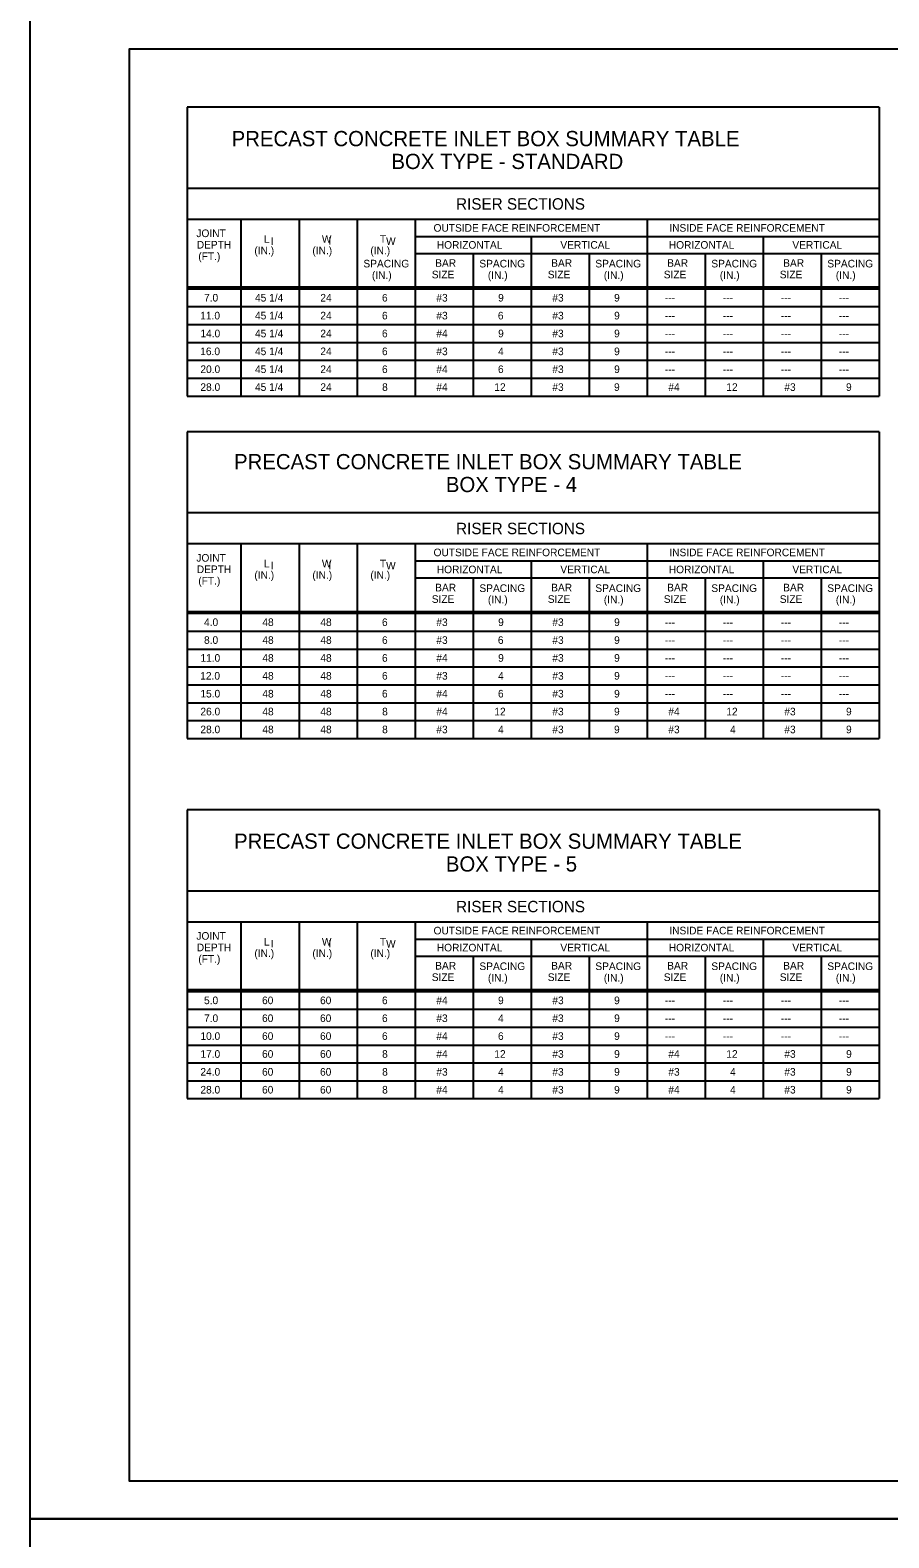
# Model space of a CAD drawing. Extents: x -6420 to 49575, y -4552 to 11624.
# Drawn here: x -6420 to -5310, y -94 to 1855 of the extents above; entities that cross this region are included whole.
import ezdxf

# ---------------------------------------------------------------- set-up
doc = ezdxf.new("R2010")
doc.units = 0
doc.layers.add('1', color=7, linetype='Continuous')
doc.layers.add('PLT-BNDY', color=7, linetype='Continuous')

msp = doc.modelspace()

# ---------------------------------------------------------------- linework, layer by layer
at = {"layer": '1'}
for p, q in [((-6217.4, 1755.6), (-6217.4, 1382.3)), ((-5322.4, 1755.6), (-6217.4, 1755.6)), ((-5322.4, 1755.6), (-5322.4, 1382.3)), ((-5322.4, 1650.6), (-6217.4, 1650.6)), ((-5322.4, 1610.6), (-6217.4, 1610.6)), ((-6147.4, 1382.3), (-6147.4, 1610.6)), ((-6072.4, 1610.6), (-6072.4, 1382.3)), ((-5997.4, 1610.6), (-5997.4, 1382.3)), ((-5922.4, 1610.6), (-5922.4, 1382.3)), ((-5622.4, 1610.6), (-5622.4, 1382.3)), ((-5922.4, 1588.6), (-5622.4, 1588.6)), ((-5772.4, 1588.6), (-5772.4, 1382.3)), ((-5622.4, 1588.6), (-5322.4, 1588.6)), ((-5472.4, 1588.6), (-5472.4, 1382.3)), ((-5922.4, 1566.6), (-5622.4, 1566.6)), ((-5847.4, 1566.6), (-5847.4, 1382.3)), ((-5697.4, 1566.6), (-5697.4, 1382.3)), ((-5622.4, 1566.6), (-5322.4, 1566.6)), ((-5547.4, 1566.6), (-5547.4, 1382.3)), ((-5397.4, 1566.6), (-5397.4, 1382.3)), ((-6217.4, 1523.4), (-5322.4, 1523.4)), ((-6217.4, 1520.9), (-5322.4, 1520.9)), ((-6217.4, 1497.8), (-5322.4, 1497.8)), ((-6217.4, 1474.7), (-5322.4, 1474.7)), ((-6217.4, 1451.6), (-5322.4, 1451.6)), ((-6217.4, 1428.5), (-5322.4, 1428.5)), ((-6217.4, 1405.4), (-5322.4, 1405.4)), ((-6217.4, 1382.3), (-5322.4, 1382.3)), ((-6217.4, 1336.1), (-6217.4, 939.7)), ((-5322.4, 1336.1), (-6217.4, 1336.1)), ((-5322.4, 1336.1), (-5322.4, 939.7)), ((-5322.4, 1231.1), (-6217.4, 1231.1)), ((-5322.4, 1191.1), (-6217.4, 1191.1)), ((-6147.4, 939.7), (-6147.4, 1191.1)), ((-6072.4, 1191.1), (-6072.4, 939.7)), ((-5997.4, 1191.1), (-5997.4, 939.7)), ((-5922.4, 1191.1), (-5922.4, 939.7)), ((-5622.4, 1191.1), (-5622.4, 939.7)), ((-5922.4, 1169.1), (-5622.4, 1169.1)), ((-5772.4, 1169.1), (-5772.4, 939.7)), ((-5622.4, 1169.1), (-5322.4, 1169.1)), ((-5472.4, 1169.1), (-5472.4, 939.7)), ((-5922.4, 1147.1), (-5622.4, 1147.1)), ((-5847.4, 1147.1), (-5847.4, 939.7)), ((-5697.4, 1147.1), (-5697.4, 939.7)), ((-5622.4, 1147.1), (-5322.4, 1147.1)), ((-5547.4, 1147.1), (-5547.4, 939.7)), ((-5397.4, 1147.1), (-5397.4, 939.7)), ((-6217.4, 1103.9), (-5322.4, 1103.9)), ((-6217.4, 1101.4), (-5322.4, 1101.4)), ((-6217.4, 1078.3), (-5322.4, 1078.3)), ((-6217.4, 1055.2), (-5322.4, 1055.2)), ((-6217.4, 1032.1), (-5322.4, 1032.1)), ((-6217.4, 1009), (-5322.4, 1009)), ((-6217.4, 985.9), (-5322.4, 985.9)), ((-6217.4, 962.8), (-5322.4, 962.8)), ((-6217.4, 939.7), (-5322.4, 939.7)), ((-6217.4, 847.3), (-6217.4, 474.1)), ((-5322.4, 847.3), (-6217.4, 847.3)), ((-5322.4, 847.3), (-5322.4, 474.1)), ((-5322.4, 742.4), (-6217.4, 742.4)), ((-5322.4, 702.4), (-6217.4, 702.4)), ((-6147.4, 474.1), (-6147.4, 702.4)), ((-6072.4, 702.4), (-6072.4, 474.1)), ((-5997.4, 702.4), (-5997.4, 474.1)), ((-5922.4, 702.4), (-5922.4, 474.1)), ((-5622.4, 702.4), (-5622.4, 474.1)), ((-5922.4, 680.4), (-5622.4, 680.4)), ((-5772.4, 680.4), (-5772.4, 474.1)), ((-5622.4, 680.4), (-5322.4, 680.4)), ((-5472.4, 680.4), (-5472.4, 474.1)), ((-5922.4, 658.4), (-5622.4, 658.4)), ((-5847.4, 658.4), (-5847.4, 474.1)), ((-5697.4, 658.4), (-5697.4, 474.1)), ((-5622.4, 658.4), (-5322.4, 658.4)), ((-5547.4, 658.4), (-5547.4, 474.1)), ((-5397.4, 658.4), (-5397.4, 474.1)), ((-6217.4, 615.1), (-5322.4, 615.1)), ((-6217.4, 612.7), (-5322.4, 612.7)), ((-6217.4, 589.6), (-5322.4, 589.6)), ((-6217.4, 566.5), (-5322.4, 566.5)), ((-6217.4, 543.4), (-5322.4, 543.4)), ((-6217.4, 520.3), (-5322.4, 520.3)), ((-6217.4, 497.2), (-5322.4, 497.2)), ((-6217.4, 474.1), (-5322.4, 474.1))]:
    msp.add_line(p, q, dxfattribs=at)
msp.add_lwpolyline([(-3713.7, -19.8), (-3713.7, 1830.6), (-6292.4, 1830.6), (-6292.4, -19.8), (-3713.7, -19.8), (-3713.7, 66.7), (-4369.8, 66.7), (-4369.8, 278.9), (-3713.7, 278.9), (-3713.7, 373.9), (-4369.8, 373.9), (-4369.8, -19.8), (-4111.3, -19.8), (-4111.3, 66.7), (-4111.3, -19.8), (-3858.7, -19.8), (-3858.7, 66.7), (-3858.7, 26.3), (-3713.7, 26.3)], dxfattribs=at)
at = {"layer": 'PLT-BNDY'}
for points in [[(-6420.4, 1879.8), (-3661.2, 1879.8), (-3661.2, -69), (-6420.4, -69)], [(-6420.4, -69), (-3661.2, -69), (-3661.2, -2017.8), (-6420.4, -2017.8)]]:
    msp.add_lwpolyline(points, close=True, dxfattribs=at)

# ---------------------------------------------------------------- texts
at = {"layer": '1'}
for s, height, p in [('PRECAST CONCRETE INLET BOX SUMMARY TABLE', 19.685, (-6159.8, 1705.2)), ('BOX TYPE - STANDARD', 19.685, (-5953.2, 1675.7)), ('RISER SECTIONS', 14.764, (-5869.6, 1623.2)), ('OUTSIDE FACE REINFORCEMENT', 9.843, (-5898.7, 1594.7)), ('INSIDE FACE REINFORCEMENT', 9.843, (-5593.8, 1594.7)), ('JOINT', 9.84, (-6205.4, 1587.7)), ('DEPTH', 9.84, (-6204.9, 1572.9)), ('L ', 9.84, (-6118.1, 1580.3)), ('I', 9.84, (-6109.1, 1577.7)), ('W ', 9.84, (-6043.1, 1580.3)), ('I', 9.84, (-6034.7, 1577.8)), ('T ', 9.84, (-5968.1, 1580.3)), ('W', 9.84, (-5960.1, 1577.6)), ('HORIZONTAL', 9.84, (-5894.5, 1572.7)), ('VERTICAL', 9.84, (-5734.7, 1572.7)), ('HORIZONTAL', 9.84, (-5594.5, 1572.7)), ('VERTICAL', 9.84, (-5434.7, 1572.7)), ('(FT.)', 9.84, (-6202.9, 1558)), ('(IN.)', 9.84, (-6130.4, 1565.5)), ('(IN.)', 9.84, (-6055.4, 1565.5)), ('(IN.)', 9.84, (-5980.4, 1565.5)), ('BAR', 9.84, (-5896.6, 1549.3)), ('BAR', 9.84, (-5746.6, 1549.3)), ('BAR', 9.84, (-5596.6, 1549.3)), ('BAR', 9.84, (-5446.6, 1549.3)), ('SPACING', 9.84, (-5989.4, 1548.5)), ('(IN.)', 9.84, (-5978.4, 1533.7)), ('SIZE', 9.84, (-5901, 1534.4)), ('SPACING', 9.84, (-5839.5, 1548.5)), ('(IN.)', 9.84, (-5828.5, 1533.7)), ('SIZE', 9.84, (-5751, 1534.4)), ('SPACING', 9.84, (-5689.5, 1548.5)), ('(IN.)', 9.84, (-5678.5, 1533.7)), ('SIZE', 9.84, (-5601, 1534.4)), ('SPACING', 9.84, (-5539.5, 1548.5)), ('(IN.)', 9.84, (-5528.5, 1533.7)), ('SIZE', 9.84, (-5451, 1534.4)), ('SPACING', 9.84, (-5389.5, 1548.5)), ('(IN.)', 9.84, (-5378.5, 1533.7)), ('7.0', 9.84, (-6195.5, 1504.4)), ('45 1/4', 9.84, (-6129.6, 1504.4)), ('24', 9.84, (-6045.1, 1504.4)), ('6', 9.84, (-5965.4, 1504.4)), ('#3', 9.84, (-5895.1, 1504.4)), ('9', 9.84, (-5815.2, 1504.4)), ('#3', 9.84, (-5745.1, 1504.4)), ('9', 9.84, (-5665.2, 1504.4)), ('---', 9.84, (-5599.6, 1504.4)), ('---', 9.84, (-5524.6, 1504.4)), ('---', 9.84, (-5449.6, 1504.4)), ('---', 9.84, (-5374.6, 1504.4)), ('11.0', 9.84, (-6200.4, 1481.3)), ('45 1/4', 9.84, (-6129.6, 1481.3)), ('24', 9.84, (-6045.1, 1481.3)), ('6', 9.84, (-5965.4, 1481.3)), ('#3', 9.84, (-5895.1, 1481.3)), ('6', 9.84, (-5815.5, 1481.3)), ('#3', 9.84, (-5745.1, 1481.3)), ('9', 9.84, (-5665.2, 1481.3)), ('---', 9.84, (-5599.6, 1481.3)), ('---', 9.84, (-5524.6, 1481.3)), ('---', 9.84, (-5449.6, 1481.3)), ('---', 9.84, (-5374.6, 1481.3)), ('14.0', 9.84, (-6200.2, 1458.2)), ('45 1/4', 9.84, (-6129.6, 1458.2)), ('24', 9.84, (-6045.1, 1458.2)), ('6', 9.84, (-5965.4, 1458.2)), ('#4', 9.84, (-5895.1, 1458.2)), ('9', 9.84, (-5815.2, 1458.2)), ('#3', 9.84, (-5745.1, 1458.2)), ('9', 9.84, (-5665.2, 1458.2)), ('---', 9.84, (-5599.6, 1458.2)), ('---', 9.84, (-5524.6, 1458.2)), ('---', 9.84, (-5449.6, 1458.2)), ('---', 9.84, (-5374.6, 1458.2)), ('16.0', 9.84, (-6200.4, 1435.1)), ('45 1/4', 9.84, (-6129.6, 1435.1)), ('24', 9.84, (-6045.1, 1435.1)), ('6', 9.84, (-5965.4, 1435.1)), ('#3', 9.84, (-5895.1, 1435.1)), ('4', 9.84, (-5815.2, 1435.1)), ('#3', 9.84, (-5745.1, 1435.1)), ('9', 9.84, (-5665.2, 1435.1)), ('---', 9.84, (-5599.6, 1435.1)), ('---', 9.84, (-5524.6, 1435.1)), ('---', 9.84, (-5449.6, 1435.1)), ('---', 9.84, (-5374.6, 1435.1)), ('20.0', 9.84, (-6200.2, 1412)), ('45 1/4', 9.84, (-6129.6, 1412)), ('24', 9.84, (-6045.1, 1412)), ('6', 9.84, (-5965.4, 1412)), ('#4', 9.84, (-5895.1, 1412)), ('6', 9.84, (-5815.4, 1412)), ('#3', 9.84, (-5745.1, 1412)), ('9', 9.84, (-5665.2, 1412)), ('---', 9.84, (-5599.6, 1412)), ('---', 9.84, (-5524.6, 1412)), ('---', 9.84, (-5449.6, 1412)), ('---', 9.84, (-5374.6, 1412)), ('28.0', 9.84, (-6200.2, 1388.9)), ('45 1/4', 9.84, (-6129.6, 1388.9)), ('24', 9.84, (-6045.1, 1388.9)), ('8', 9.84, (-5965.2, 1388.9)), ('#4', 9.84, (-5895.1, 1388.9)), ('12', 9.84, (-5820.1, 1388.9)), ('#3', 9.84, (-5745.1, 1388.9)), ('9', 9.84, (-5665.3, 1388.9)), ('#4', 9.84, (-5595.1, 1388.9)), ('12', 9.84, (-5520.1, 1388.9)), ('#3', 9.84, (-5445.1, 1388.9)), ('9', 9.84, (-5365.3, 1388.9)), ('PRECAST CONCRETE INLET BOX SUMMARY TABLE', 19.685, (-6156.7, 1287.6)), ('BOX TYPE - 4', 19.685, (-5882.8, 1258.1)), ('RISER SECTIONS', 14.764, (-5869.6, 1203.7)), ('JOINT', 9.84, (-6205.4, 1168.2)), ('L ', 9.84, (-6118.1, 1160.8)), ('W ', 9.84, (-6043.1, 1160.8)), ('T ', 9.84, (-5968.1, 1160.8)), ('OUTSIDE FACE REINFORCEMENT', 9.843, (-5898.7, 1175.2)), ('INSIDE FACE REINFORCEMENT', 9.843, (-5593.8, 1175.2)), ('DEPTH', 9.84, (-6204.9, 1153.4)), ('(IN.)', 9.84, (-6130.4, 1146)), ('I', 9.84, (-6109.1, 1158.3)), ('(IN.)', 9.84, (-6055.4, 1146)), ('I', 9.84, (-6034.7, 1158.3)), ('(IN.)', 9.84, (-5980.4, 1146)), ('W', 9.84, (-5960.1, 1158.1)), ('HORIZONTAL', 9.84, (-5894.5, 1153.2)), ('VERTICAL', 9.84, (-5734.7, 1153.2)), ('HORIZONTAL', 9.84, (-5594.5, 1153.2)), ('VERTICAL', 9.84, (-5434.7, 1153.2)), ('(FT.)', 9.84, (-6202.9, 1138.6)), ('BAR', 9.84, (-5896.6, 1129.8)), ('SPACING', 9.84, (-5839.4, 1129)), ('BAR', 9.84, (-5746.6, 1129.8)), ('SPACING', 9.84, (-5689.5, 1129)), ('BAR', 9.84, (-5596.6, 1129.8)), ('SPACING', 9.84, (-5539.5, 1129)), ('BAR', 9.84, (-5446.6, 1129.8)), ('SPACING', 9.84, (-5389.5, 1129)), ('SIZE', 9.84, (-5901, 1114.9)), ('(IN.)', 9.84, (-5828.4, 1114.2)), ('SIZE', 9.84, (-5751, 1114.9)), ('(IN.)', 9.84, (-5678.5, 1114.2)), ('SIZE', 9.84, (-5601, 1114.9)), ('(IN.)', 9.84, (-5528.5, 1114.2)), ('SIZE', 9.84, (-5451, 1114.9)), ('(IN.)', 9.84, (-5378.5, 1114.2)), ('4.0', 9.84, (-6195.5, 1085)), ('48', 9.84, (-6120.1, 1085)), ('48', 9.84, (-6045.1, 1085)), ('6', 9.84, (-5965.4, 1085)), ('#3', 9.84, (-5895.1, 1085)), ('9', 9.84, (-5815.2, 1085)), ('#3', 9.84, (-5745.1, 1085)), ('9', 9.84, (-5665.2, 1085)), ('#3', 9.84, (-5745.1, 1061.9)), ('---', 9.84, (-5599.6, 1085)), ('---', 9.84, (-5524.6, 1085)), ('---', 9.84, (-5449.6, 1085)), ('---', 9.84, (-5374.6, 1085)), ('8.0', 9.84, (-6195.5, 1061.9)), ('48', 9.84, (-6120.1, 1061.9)), ('48', 9.84, (-6045.1, 1061.9)), ('6', 9.84, (-5965.4, 1061.9)), ('#3', 9.84, (-5895.1, 1061.9)), ('6', 9.84, (-5815.5, 1061.9)), ('9', 9.84, (-5665.2, 1061.9)), ('---', 9.84, (-5599.6, 1061.9)), ('---', 9.84, (-5524.6, 1061.9)), ('---', 9.84, (-5449.6, 1061.9)), ('---', 9.84, (-5374.6, 1061.9)), ('11.0', 9.84, (-6200.2, 1038.8)), ('48', 9.84, (-6120.1, 1038.8)), ('48', 9.84, (-6045.1, 1038.8)), ('6', 9.84, (-5965.4, 1038.8)), ('#4', 9.84, (-5895.1, 1038.8)), ('9', 9.84, (-5815.2, 1038.8)), ('#3', 9.84, (-5745.1, 1038.8)), ('9', 9.84, (-5665.2, 1038.8)), ('---', 9.84, (-5599.6, 1038.8)), ('---', 9.84, (-5524.6, 1038.8)), ('---', 9.84, (-5449.6, 1038.8)), ('---', 9.84, (-5374.6, 1038.8)), ('12.0', 9.84, (-6200.4, 1015.7)), ('48', 9.84, (-6120.1, 1015.7)), ('48', 9.84, (-6045.1, 1015.7)), ('6', 9.84, (-5965.4, 1015.7)), ('#3', 9.84, (-5895.1, 1015.7)), ('4', 9.84, (-5815.2, 1015.7)), ('#3', 9.84, (-5745.1, 1015.7)), ('9', 9.84, (-5665.2, 1015.7)), ('---', 9.84, (-5599.6, 1015.7)), ('---', 9.84, (-5524.6, 1015.7)), ('---', 9.84, (-5449.6, 1015.7)), ('---', 9.84, (-5374.6, 1015.7)), ('15.0', 9.84, (-6200.2, 992.6)), ('48', 9.84, (-6120.1, 992.6)), ('48', 9.84, (-6045.1, 992.6)), ('6', 9.84, (-5965.4, 992.6)), ('#4', 9.84, (-5895.1, 992.6)), ('6', 9.84, (-5815.4, 992.6)), ('#3', 9.84, (-5745.1, 992.6)), ('9', 9.84, (-5665.2, 992.6)), ('---', 9.84, (-5599.6, 992.6)), ('---', 9.84, (-5524.6, 992.6)), ('---', 9.84, (-5449.6, 992.6)), ('---', 9.84, (-5374.6, 992.6)), ('26.0', 9.84, (-6200.2, 969.5)), ('48', 9.84, (-6120.1, 969.5)), ('48', 9.84, (-6045.1, 969.5)), ('8', 9.84, (-5965.2, 969.5)), ('#4', 9.84, (-5895.1, 969.5)), ('12', 9.84, (-5820.1, 969.5)), ('#3', 9.84, (-5745.1, 969.5)), ('9', 9.84, (-5665.3, 969.5)), ('#4', 9.84, (-5595.1, 969.5)), ('12', 9.84, (-5520.1, 969.5)), ('#3', 9.84, (-5445.1, 969.5)), ('9', 9.84, (-5365.3, 969.5)), ('28.0', 9.84, (-6200.2, 946.4)), ('48', 9.84, (-6120.1, 946.4)), ('48', 9.84, (-6045.1, 946.4)), ('8', 9.84, (-5965.2, 946.4)), ('#3', 9.84, (-5895.1, 946.4)), ('4', 9.84, (-5815.2, 946.4)), ('#3', 9.84, (-5745.1, 946.4)), ('9', 9.84, (-5665.3, 946.4)), ('#3', 9.84, (-5595.1, 946.4)), ('4', 9.84, (-5515.2, 946.4)), ('#3', 9.84, (-5445.1, 946.4)), ('9', 9.84, (-5365.3, 946.4)), ('PRECAST CONCRETE INLET BOX SUMMARY TABLE', 19.685, (-6156.7, 797.1)), ('BOX TYPE - 5', 19.685, (-5882.8, 767.6)), ('RISER SECTIONS', 14.764, (-5869.6, 715)), ('JOINT', 9.84, (-6205.4, 679.5)), ('OUTSIDE FACE REINFORCEMENT', 9.843, (-5898.7, 686.4)), ('INSIDE FACE REINFORCEMENT', 9.843, (-5593.8, 686.4)), ('DEPTH', 9.84, (-6204.9, 664.6)), ('(IN.)', 9.84, (-6130.4, 657.2)), ('L ', 9.84, (-6118.1, 672)), ('I', 9.84, (-6109.1, 669.5)), ('(IN.)', 9.84, (-6055.4, 657.2)), ('W ', 9.84, (-6043.1, 672)), ('I', 9.84, (-6034.7, 669.5)), ('(IN.)', 9.84, (-5980.4, 657.2)), ('T ', 9.84, (-5968.1, 672)), ('W', 9.84, (-5960.1, 669.4)), ('HORIZONTAL', 9.84, (-5894.5, 664.4)), ('VERTICAL', 9.84, (-5734.7, 664.4)), ('HORIZONTAL', 9.84, (-5594.5, 664.4)), ('VERTICAL', 9.84, (-5434.7, 664.4)), ('(FT.)', 9.84, (-6202.9, 649.8)), ('BAR', 9.84, (-5896.6, 641)), ('SPACING', 9.84, (-5839.4, 640.3)), ('BAR', 9.84, (-5746.6, 641)), ('SPACING', 9.84, (-5689.5, 640.3)), ('BAR', 9.84, (-5596.6, 641)), ('SPACING', 9.84, (-5539.5, 640.3)), ('BAR', 9.84, (-5446.6, 641)), ('SPACING', 9.84, (-5389.5, 640.3)), ('SIZE', 9.84, (-5901, 626.2)), ('(IN.)', 9.84, (-5828.4, 625.4)), ('SIZE', 9.84, (-5751, 626.2)), ('(IN.)', 9.84, (-5678.5, 625.4)), ('SIZE', 9.84, (-5601, 626.2)), ('(IN.)', 9.84, (-5528.5, 625.4)), ('SIZE', 9.84, (-5451, 626.2)), ('(IN.)', 9.84, (-5378.5, 625.4)), ('5.0', 9.84, (-6195.5, 596.2)), ('60', 9.84, (-6120.5, 596.2)), ('60', 9.84, (-6045.5, 596.2)), ('6', 9.84, (-5965.4, 596.2)), ('#4', 9.84, (-5895.1, 596.2)), ('9', 9.84, (-5815.3, 596.2)), ('#3', 9.84, (-5745.1, 596.2)), ('9', 9.84, (-5665.2, 596.2)), ('---', 9.84, (-5599.6, 596.2)), ('---', 9.84, (-5524.6, 596.2)), ('---', 9.84, (-5449.6, 596.2)), ('---', 9.84, (-5374.6, 596.2)), ('7.0', 9.84, (-6195.5, 573.1)), ('60', 9.84, (-6120.5, 573.1)), ('60', 9.84, (-6045.5, 573.1)), ('6', 9.84, (-5965.4, 573.1)), ('#3', 9.84, (-5895.1, 573.1)), ('4', 9.84, (-5815.2, 573.1)), ('#3', 9.84, (-5745.1, 573.1)), ('9', 9.84, (-5665.2, 573.1)), ('---', 9.84, (-5599.6, 573.1)), ('---', 9.84, (-5524.6, 573.1)), ('---', 9.84, (-5449.6, 573.1)), ('---', 9.84, (-5374.6, 573.1)), ('10.0', 9.84, (-6200.2, 550)), ('60', 9.84, (-6120.5, 550)), ('60', 9.84, (-6045.5, 550)), ('6', 9.84, (-5965.4, 550)), ('#4', 9.84, (-5895.1, 550)), ('6', 9.84, (-5815.4, 550)), ('#3', 9.84, (-5745.1, 550)), ('9', 9.84, (-5665.2, 550)), ('---', 9.84, (-5599.6, 550)), ('---', 9.84, (-5524.6, 550)), ('---', 9.84, (-5449.6, 550)), ('---', 9.84, (-5374.6, 550)), ('17.0', 9.84, (-6200.2, 526.9)), ('60', 9.84, (-6120.5, 526.9)), ('60', 9.84, (-6045.5, 526.9)), ('8', 9.84, (-5965.2, 526.9)), ('#4', 9.84, (-5895.1, 526.9)), ('12', 9.84, (-5820.1, 526.9)), ('#3', 9.84, (-5745.1, 526.9)), ('9', 9.84, (-5665.2, 526.9)), ('#4', 9.84, (-5595.1, 526.9)), ('12', 9.84, (-5520.1, 526.9)), ('#3', 9.84, (-5445.1, 526.9)), ('9', 9.84, (-5365.2, 526.9)), ('24.0', 9.84, (-6200.2, 503.8)), ('60', 9.84, (-6120.5, 503.8)), ('60', 9.84, (-6045.5, 503.8)), ('8', 9.84, (-5965.2, 503.8)), ('#3', 9.84, (-5895.1, 503.8)), ('4', 9.84, (-5815.2, 503.8)), ('#3', 9.84, (-5745.1, 503.8)), ('9', 9.84, (-5665.2, 503.8)), ('#3', 9.84, (-5595.1, 503.8)), ('4', 9.84, (-5515.2, 503.8)), ('#3', 9.84, (-5445.1, 503.8)), ('9', 9.84, (-5365.2, 503.8)), ('28.0', 9.84, (-6200.2, 480.7)), ('60', 9.84, (-6120.5, 480.7)), ('60', 9.84, (-6045.5, 480.7)), ('8', 9.84, (-5965.2, 480.7)), ('#4', 9.84, (-5895.1, 480.7)), ('4', 9.84, (-5815.2, 480.7)), ('#3', 9.84, (-5745.1, 480.7)), ('9', 9.84, (-5665.2, 480.7)), ('#4', 9.84, (-5595.1, 480.7)), ('4', 9.84, (-5515.2, 480.7)), ('#3', 9.84, (-5445.1, 480.7)), ('9', 9.84, (-5365.2, 480.7))]:
    msp.add_text(s, height=height, dxfattribs=at).set_placement(p)

doc.saveas('drawing.dxf')
